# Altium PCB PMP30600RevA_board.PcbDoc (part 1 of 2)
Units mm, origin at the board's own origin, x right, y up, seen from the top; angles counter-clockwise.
Board outline 78.5 x 61.5 mm, 4 copper layers (Top Layer, 2nd Layer, 3rd Layer, Bottom Layer), stack 2.155 mm thick; 62 components, 27 nets, 174 pads, 413 vias.
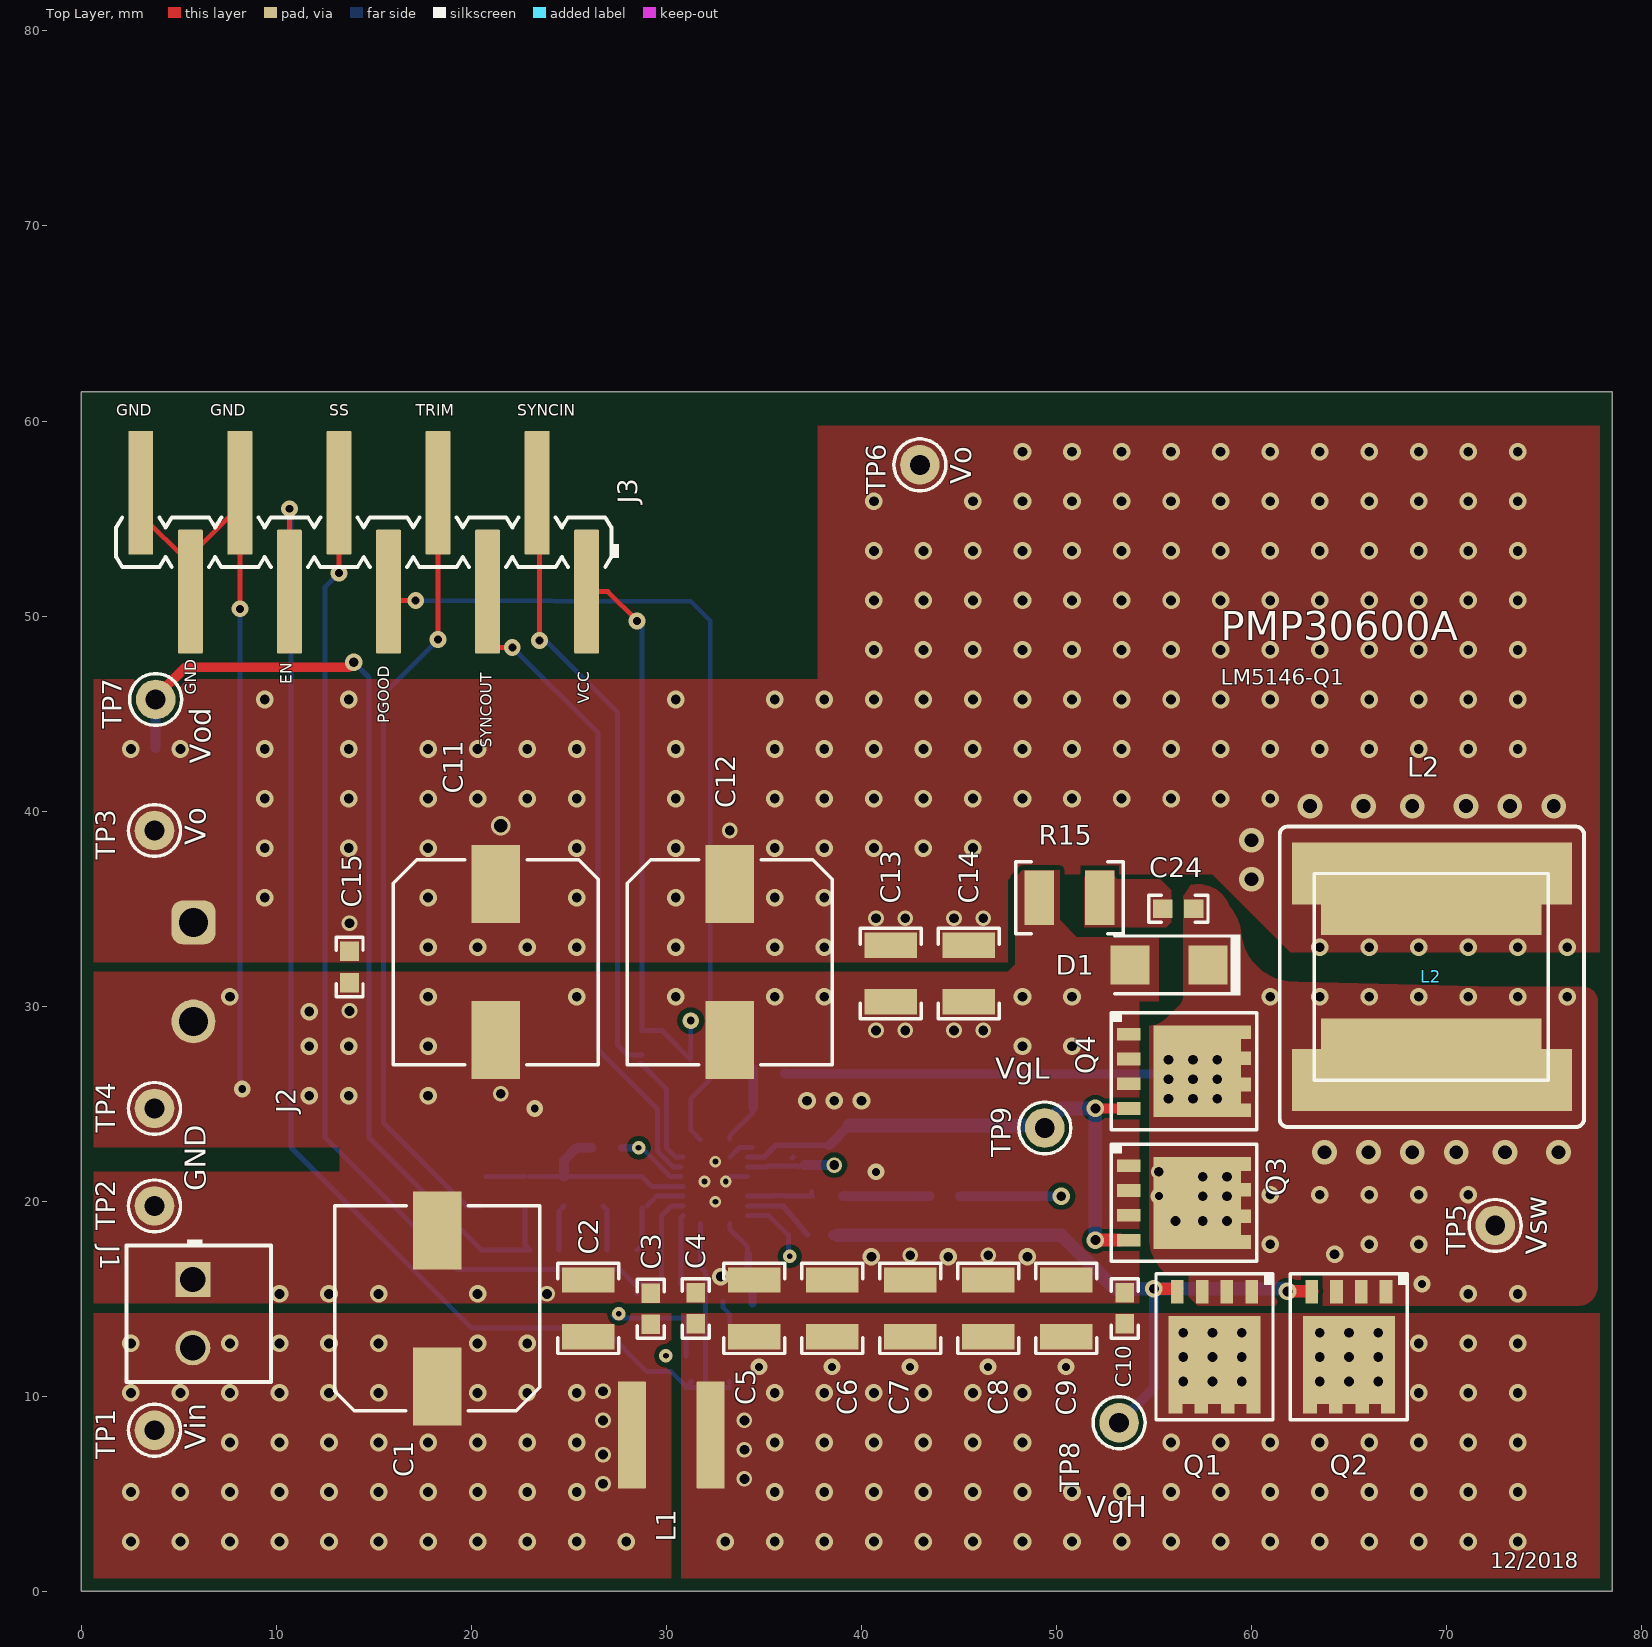
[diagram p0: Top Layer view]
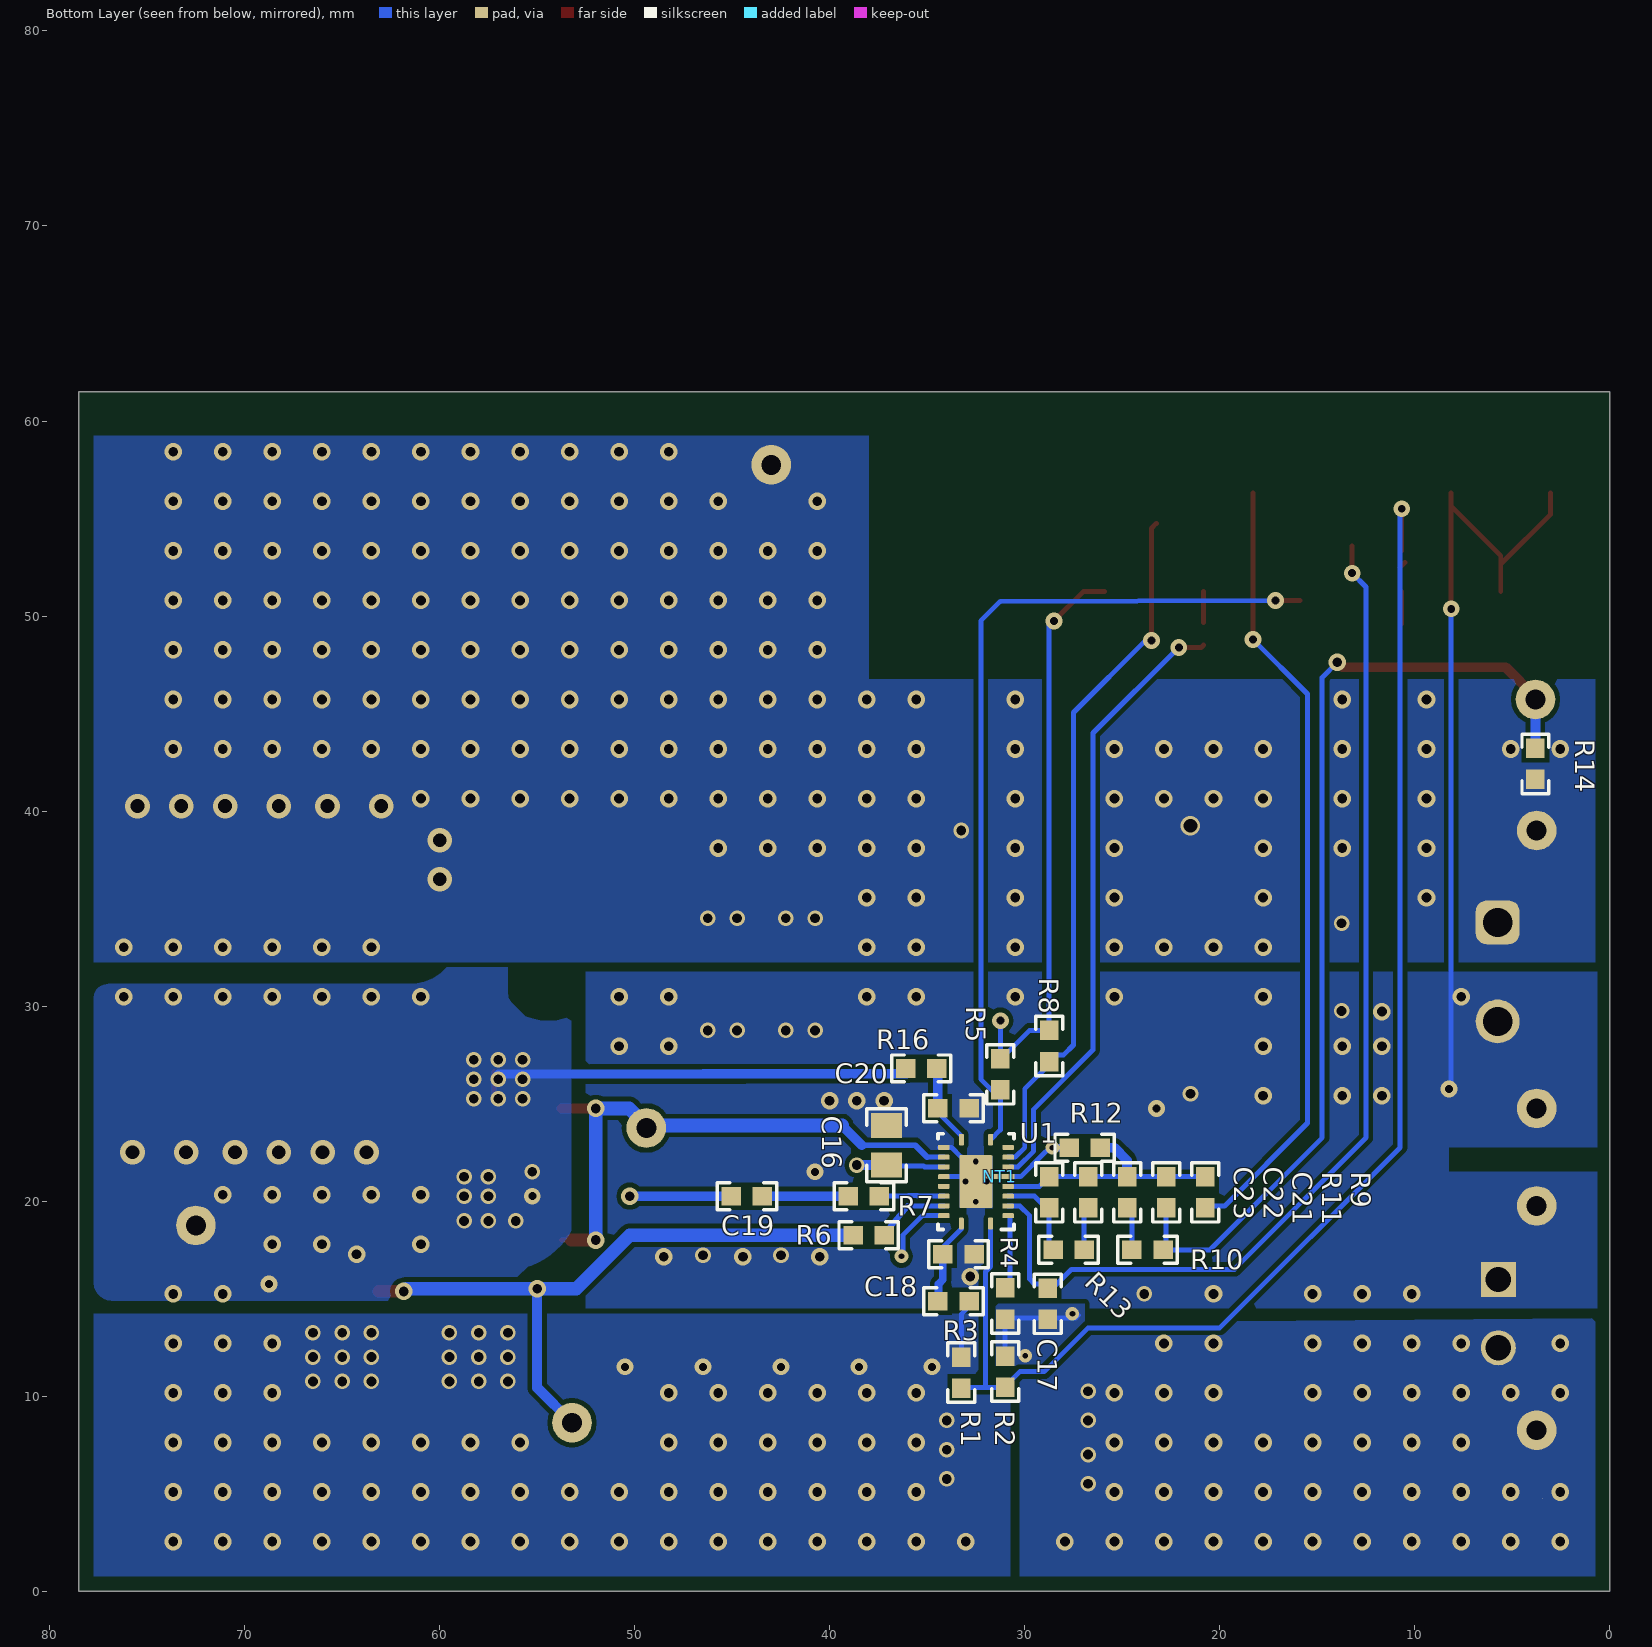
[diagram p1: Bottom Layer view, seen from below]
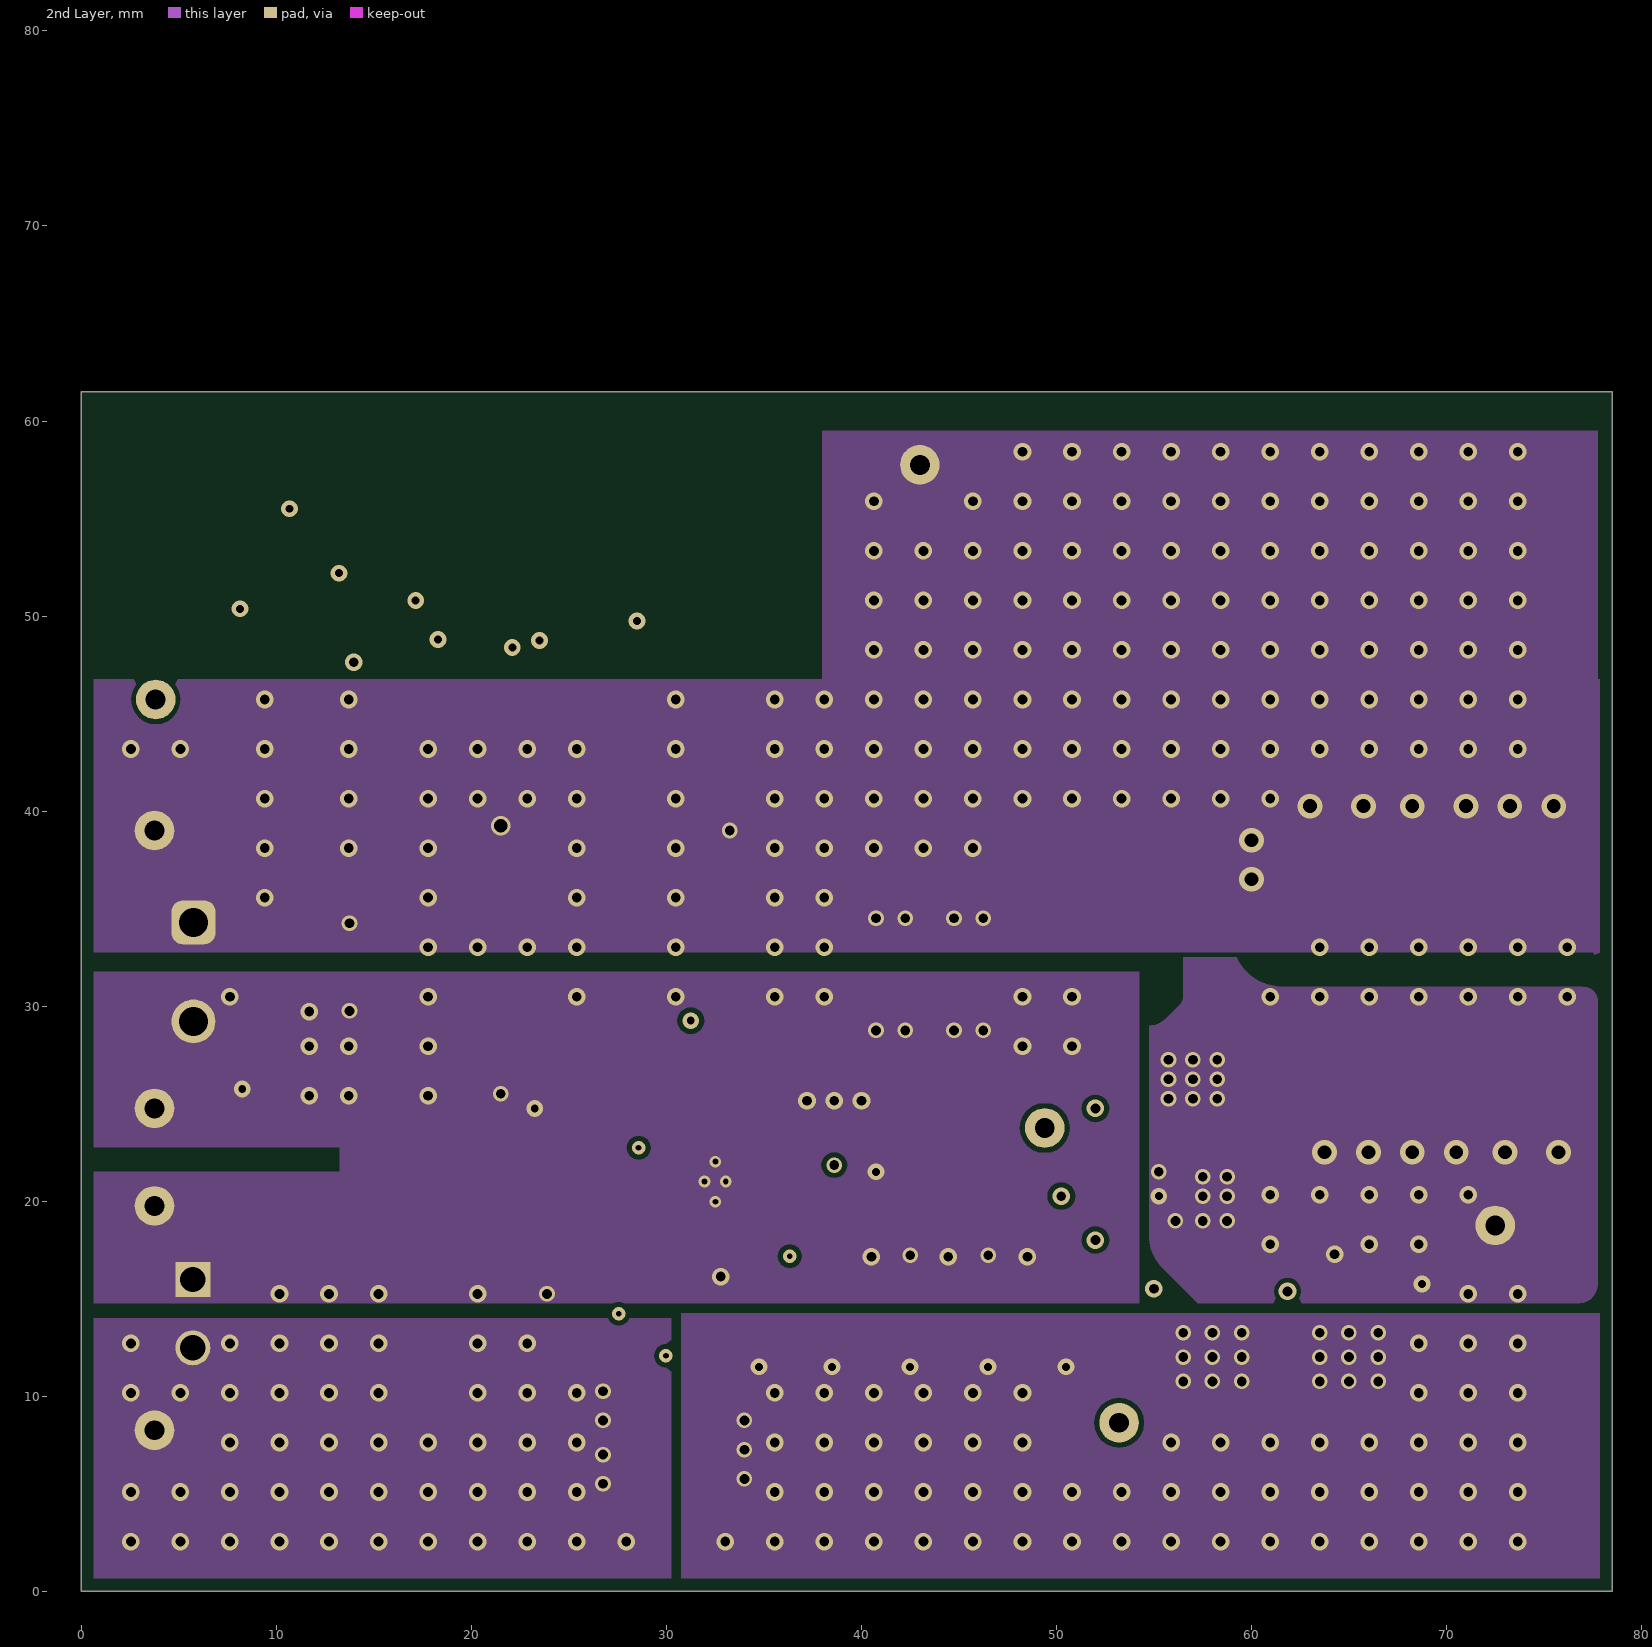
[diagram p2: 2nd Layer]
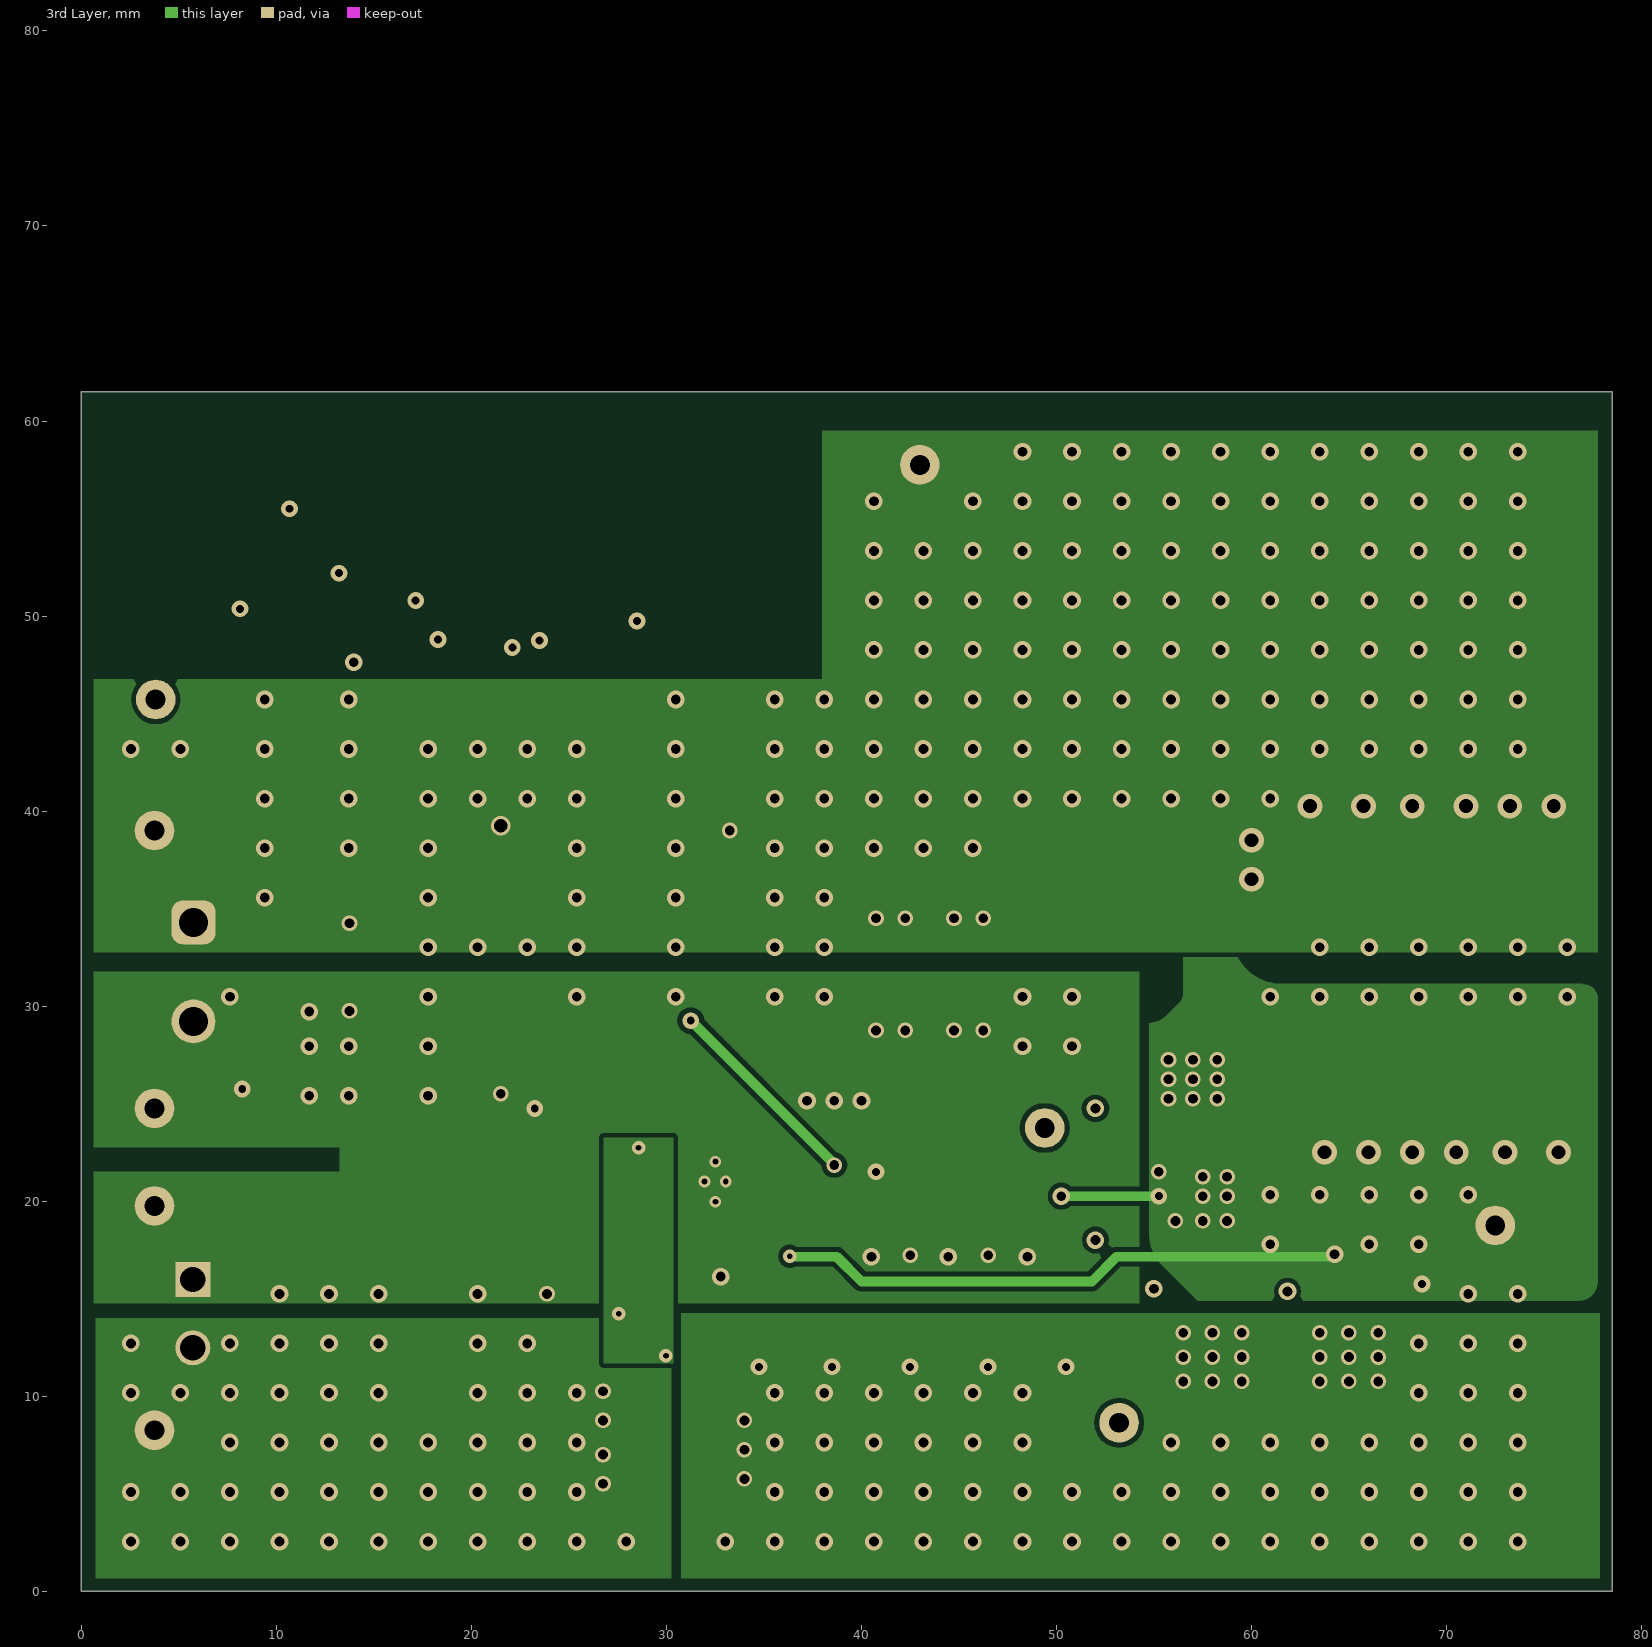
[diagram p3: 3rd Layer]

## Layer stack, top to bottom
Top Solder: solder mask 0.0102, Solder Resist, Dk 3.5
Top Layer: signal copper 0.0356
Dielectric 2: dielectric 0.254, Dk 4.2
2nd Layer: signal copper 0.036
Dielectric1: core 1.5037, FR-4, Dk 4.8
3rd Layer: signal copper 0.036
Dielectric 3: dielectric 0.254, Dk 4.2
Bottom Layer: signal copper 0.0356
Bottom Solder: solder mask 0.0102, Solder Resist, Dk 3.5

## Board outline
0,0 78.5,0 78.5,61.5 0,61.5
cut-out: 3.442,4.75
cut-out: 3.442,4.75

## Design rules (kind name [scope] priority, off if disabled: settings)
AcuteAngle [All] p1: minimum=4.50000000000000E+0001 checktracksonly=FALSE
AssemblyTestPointUsage [All] p1: valid=2
BoardOutlineClearance BoardOutlineClearance_MountingHoles [OnCopper and InComponentClass('Mounting Holes')] p1: gap=1 ignorepadtopadclearanceinfootprint=FALSE
BoardOutlineClearance BoardOutlineClearance_Poly [OnCopper and IsPoly] p2: gap=0.635 ignorepadtopadclearanceinfootprint=FALSE
BoardOutlineClearance [OnCopper and Not InComponentClass('Logo') and not InComponentClass('FiducialMark') and not InRegion(1000,500,4000,800) and not InPoly] p3: gap=1.905 ignorepadtopadclearanceinfootprint=FALSE
Clearance Clearance_Keepouts [((IsTrack Or IsArc) And Not InPoly) And IsFree and IsKeepOut vs ((IsTrack Or IsArc) And Not InPoly) And IsFree and IsKeepOut] p1: gap=0 ignorepadtopadclearanceinfootprint=FALSE
Clearance Clearance_Poly [InPolygon] p2: gap=0.25 ignorepadtopadclearanceinfootprint=TRUE
Clearance Clearance_FiducialMark [IsKeepOut and InComponentClass('FiducialMark') vs IsPad and InComponentClass('FiducialMark')] p3: gap=0 ignorepadtopadclearanceinfootprint=FALSE
Clearance [All] p4: gap=0.2 ignorepadtopadclearanceinfootprint=TRUE
ComponentClearance ComponentClearance_MountingHoles_FiducialMarks [InComponentClass('Mounting Holes') vs InComponentClass('FiducialMark')] p1: gap=1.27 collisioncheckmode=3 verticalgap=0.254 showdistances=FALSE
ComponentClearance ComponentClearance_Shunt [InComponentClass('Header') vs InComponentClass('Shunt')] p2: gap=0 collisioncheckmode=3 verticalgap=0 showdistances=FALSE
ComponentClearance ComponentClearance_Logo [InComponentClass('Logo')] p3: gap=1.27 collisioncheckmode=3 verticalgap=0.254 showdistances=FALSE
ComponentClearance ComponentClearance_ScrewToNut [(HasFootprint('NY PMS 440 0025 PH')) vs (HasFootprint('Keystone_1902C'))] p4: gap=0.127 collisioncheckmode=3 verticalgap=0.254 showdistances=FALSE
ComponentClearance ComponentClearance_MountingHoles [InComponentClass('Mounting Holes')] p5: gap=6.35 collisioncheckmode=3 verticalgap=2540 showdistances=FALSE
ComponentClearance ComponentClearance_SmallPassives [HasFootprint('0201*') or HasFootprint('0402*') or HasFootprint('0508') or HasFootprint('0603*') or HasFootprint('0612') or HasFootprint('0805*') or HasFootprint('0815*') or HasFootprint('0830*') or HasFootprint('1206*') or HasFootprint('1210*') or HasFootprint('1808*') or HasFootprint('1812*') or HasFootprint('1825*') or HasFootprint('2010*') or HasFootprint('2220*') or HasFootprint('2225*') or HasFootprint('2512*') or HasFootprint('2728*') or HasFootprint('3518*') vs HasFootprint('0201*') or HasFootprint('0402*') or HasFootprint('0508') or HasFootprint('0603*') or HasFootprint('0612') or HasFootprint('0805*') or HasFootprint('0815*') or HasFootprint('0830*') or HasFootprint('1206*') or HasFootprint('1210*') or HasFootprint('1808*') or HasFootprint('1812*') or HasFootprint('1825*') or HasFootprint('2010*') or HasFootprint('2220*') or HasFootprint('2225*') or HasFootprint('2512*') or HasFootprint('2728*') or HasFootprint('3518*')] p6: gap=0.38 collisioncheckmode=3 verticalgap=0.254 showdistances=FALSE
ComponentClearance ComponentClearance_THtoSMT [IsThruComponent vs IsSMTComponent] p7: gap=1.016 collisioncheckmode=3 verticalgap=0.762 showdistances=FALSE
ComponentClearance ComponentClearance_THtoTH [IsThruComponent vs IsThruComponent] p8: gap=0.762 collisioncheckmode=3 verticalgap=0.762 showdistances=FALSE
ComponentClearance [All] p9: gap=0.762 collisioncheckmode=3 verticalgap=0.254 showdistances=FALSE
DiffPairsRouting [All] p1: maxlimit=2.54 minlimit=0.254 mostfreqgap=0.254 toplayer_minwidth=0.381 toplayer_maxwidth=0.381 toplayer_prefwidth=0.381 midlayer1_minwidth=0.381 midlayer1_maxwidth=0.381 midlayer1_prefwidth=0.381 midlayer2_minwidth=0.381 midlayer2_maxwidth=0.381 midlayer2_prefwidth=0.381 bottomlayer_minwidth=0.381 bottomlayer_maxwidth=0.381 bottomlayer_prefwidth=0.381 maxuncoupledlength=25.4
FabricationTestPointUsage TestPointUsage [All] p1: valid=2 allowmultiple=FALSE
FabricationTestpoint Testpoint [All] p1: side=3 testpointundercomponent=TRUE minsize=1.016 maxsize=2.54 preferedsize=1.524 minholesize=0 maxholesize=1.016 preferedholesize=0.813 testpointgrid=0.025 allowsidetop=TRUE allowsidebottom=TRUE usegrid=TRUE gridtolerance=0
FanoutControl Fanout_LCC [IsLCC] p1: bgadir=Out bgaviamode=Centered fanoutstyle=Auto fanoutdirection=Alternating viagrid=0.025 // Fanout_LCC (Default Rule)
FanoutControl Fanout_BGA [IsBGA] p2: bgadir=Out bgaviamode=Centered fanoutstyle=Auto fanoutdirection=Alternating viagrid=0.025 // Fanout_BGA (Default Rule)
FanoutControl Fanout_Default [All] p4: bgadir=Out bgaviamode=Centered fanoutstyle=Auto fanoutdirection=Alternating viagrid=0.025 // Fanout_Default (Default Rule)
FanoutControl Fanout_Small [(CompPinCount < 5)] p5: bgadir=Out bgaviamode=Centered fanoutstyle=Auto fanoutdirection=OutThenIn viagrid=0.025 // Fanout_Small (Default Rule)
HoleSize [All] p1: absolutevalues=TRUE maxlimit=6.375 minlimit=0.3 maxpercent=80.000 minpercent=20.000
MinimumAnnularRing MinimumAnnularRing_ThermalPadVias [IsVia and InAnyComponent] p1: minimumring=0.15
MinimumAnnularRing [All] p2: minimumring=0.15
MinimumSolderMaskSliver MinimumSolderMaskSliver_Logo [InComponentClass('Logo') vs InComponentClass('Logo')] p1: minsoldermaskwidth=0.018
MinimumSolderMaskSliver [All] p2: minsoldermaskwidth=0.1
PlaneConnect [All] p1: planeconnectstyle=Relief reliefexpansion=0.254 reliefentries=4 reliefconductorwidth=0.254 reliefairgap=0.254
PolygonConnect [All] p1: connectstyle=Direct reliefconductorwidth=0.254 reliefentries=4 polygonreliefangle="90 Angle" airgapwidth=0.254
RoutingVias ThermalPadVias [IsVia and InAnyComponent] p1: holewidth=0.3 width=0.5 viastyle="Through Hole" minholewidth=0.3 minwidth=0.6 maxholewidth=0.5 maxwidth=1
RoutingVias [All] p2: holewidth=0.406 width=0.864 viastyle="Through Hole" minholewidth=0.3 minwidth=0.66 maxholewidth=1.016 maxwidth=1.651
SilkToBoardRegionClearance [Not ((IsComment or IsDesignator) And (Hide <> 'False')) and not InRegion(1000,500,4000,800)] p1:
SilkToSilkClearance SilkToSilkClearance_Pb-FreeLogo [(HasFootprint('Pb-Free_Overlay_Medium') OR HasFootprint('Pb-Free_Overlay_Small')) vs (HasFootprint('Pb-Free_Overlay_Medium') OR HasFootprint('Pb-Free_Overlay_Small'))] p1: silktosilkclearance=0
SilkToSilkClearance [All] p2: silktosilkclearance=0.1
SilkToSolderMaskClearance SilkToComponentPadClearance [(IsPad or IsFill or IsRegion) and InAnycomponent] p1: minsilkscreentomaskgap=0.127 clearancetoexposedcopper=TRUE
SilkToSolderMaskClearance "Silk to Solder Mask Opening" [All] p2: minsilkscreentomaskgap=0.1 clearancetoexposedcopper=FALSE
SolderMaskExpansion [All] p1: expansion=0.05
UnRoutedNet [All] p1: checkbadconnections=TRUE
Width [All] p1: maxlimit=2.54 minlimit=0.152 preferedwidth=0.254 checkconnectedcopper=TRUE
14 further rules are at their usual default settings.

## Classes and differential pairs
component class Header: J3

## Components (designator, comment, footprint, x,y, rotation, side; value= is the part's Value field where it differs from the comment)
C1 "EEHZC1K470P" SM_RADIAL_10BMM 18.25,14.5 r90 top value=330uF
C2 "Capacitor" 1210_270 26,14.5 r90 top value=10uF
C3 "Capacitor" 0603 29.21,14.478 r90 top value=0.1uF
C4 "Capacitor" 0603 31.5,14.5 r90 top value=0.1uF
C5 "Capacitor" 1210_270 34.5,14.5 r90 top value=10uF
C6 "Capacitor" 1210_270 38.5,14.5 r90 top value=10uF
C7 "Capacitor" 1210_270 42.5,14.5 r90 top value=10uF
C8 "Capacitor" 1210_270 46.5,14.5 r90 top value=10uF
C9 "Capacitor" 1210_270 50.5,14.5 r90 top value=10uF
C10 "Capacitor" 0603 53.5,14.5 r90 top value=0.1uF
C11 "EEHZC1E331P" SM_RADIAL_10BMM 21.25,32.25 r270 top value=330uF
C12 "EEHZC1E331P" SM_RADIAL_10BMM 33.25,32.25 r270 top value=330uF
C13 "Capacitor" 1210_270 41.5,31.661 r270 top value=47uF
C14 "Capacitor" 1210_270 45.5,31.661 r270 top value=47uF
C15 "Capacitor" 0603 13.75,32 r270 top value=0.1uF
C16 "C0805C225K8RACTU" 0805_HV 37.084,22.86 r90 bottom value=2.2uF
C17 "Capacitor" 0603 28.829,14.732 r270 bottom value=0.1uF
C18 "Capacitor" 0603 33.401,17.272 r0 bottom value=0.1uF
C19 "Capacitor" 0603 44.25,20.25 r180 bottom value=0.1uF
C20 "Capacitor" 0603 33.655,24.765 r0 bottom value=0.1uF
C21 "Capacitor" 0603 24.75,20.45 r270 bottom value=0.1uF
C22 "Capacitor" 0603 26.75,20.45 r270 bottom value=0.1uF
C23 "Capacitor" 0603 28.75,20.45 r270 bottom value=0.1uF
C24 "Capacitor" 0603 56.25,35 r180 top value=1500pF
D1 "DIODE_SCHOTTKY" SMA 55.779,32.106 r180 top value=40V
J1 "691214110002" Wurth_691214110002 5.715,14.224 r270 top
J2 "691236510002" Wurth_691236510002 5.75,31.75 r270 top
J3 "GBC10SABN-M30" Sullins_GBC10SABN-M30 14.48,53.785 r180 top
L1 "XAL6060-472MEB" XAL6060 30.25,8 r180 top value=4.7uH
L2 "XAL1010-472MEB" XAL1010 69.215,31.495 r90 top value=4.7uH
L2 "XAL1580-302MEB" XAL1580 69.25,31.5 r90 top value=3uH
NT1 "Net-Tie" Net-Tie_10milWide_30milLong 31.293,21.25 r0 bottom net-tie
Q1 "MOSFET_N_D56789G4S123" PG-TDSON-8 58.106,12.531 r270 top value=40V
Q2 "MOSFET_N_D56789G4S123" PG-TDSON-8 65,12.531 r270 top value=40V
Q3 "MOSFET_N_D56789G4S123" PG-TDSON-8 56.543,19.902 r0 top value=40V
Q4 "MOSFET_N_D56789G4S123" PG-TDSON-8 56.543,26.652 r0 top value=40V
R1 "CR0603-FX-4991ELF" 0603 33.25,11.2 r90 bottom value=4.99k
R2 "CR0603-FX-4991ELF" 0603 31,11.25 r270 bottom value=4.99k
R3 "CR0603-FX-4991ELF" 0603 33.655,14.859 r180 bottom value=4.99k
R4 "CR0603-FX-4991ELF" 0603 31,14.75 r90 bottom value=4.99k
R5 "CR0603-FX-4991ELF" 0603 31.25,26.5 r90 bottom value=4.99k
R6 "CR0603-FX-4991ELF" 0603 38,18.25 r180 bottom value=4.99k
R7 "CR0603-FX-4991ELF" 0603 38.25,20.25 r180 bottom value=4.99k
R8 "CR0603-FX-4991ELF" 0603 28.75,27.95 r270 bottom value=4.99k
R9 "CR0603-FX-4991ELF" 0603 20.75,20.45 r90 bottom value=4.99k
R10 "CR0603-FX-4991ELF" 0603 23.7,17.5 r180 bottom value=4.99k
R11 "CR0603-FX-4991ELF" 0603 22.75,20.45 r270 bottom value=4.99k
R12 "CR0603-FX-4991ELF" 0603 26.924,22.733 r180 bottom value=4.99k
R13 "CR0603-FX-4991ELF" 0603 27.75,17.5 r180 bottom value=4.99k
R14 "CR0603-FX-4991ELF" 0603 3.81,42.418 r270 bottom value=4.99k
R15 "Resistor" 1210M 50.673,35.56 r0 top value=2.00
R16 "CR0603-FX-4991ELF" 0603 35.306,26.797 r180 bottom value=4.99k
TP1 "5000" Keystone5000 3.75,8.25 r90 top
TP2 "5001" Keystone5001 3.75,19.75 r90 top
TP3 "5000" Keystone5000 3.75,39 r90 top
TP4 "5001" Keystone5001 3.75,24.75 r90 top
TP5 "5003" Keystone5003 72.5,18.75 r90 top
TP6 "5002" Keystone5002 43,57.75 r90 top
TP7 "5002" Keystone5002 3.81,45.72 r90 top
TP8 "5002" Keystone5002 53.213,8.636 r90 top
TP9 "5002" Keystone5002 49.403,23.749 r90 top
U1 "LM5146QRGYRQ1" RGY0020B 32.5,21 r0 bottom

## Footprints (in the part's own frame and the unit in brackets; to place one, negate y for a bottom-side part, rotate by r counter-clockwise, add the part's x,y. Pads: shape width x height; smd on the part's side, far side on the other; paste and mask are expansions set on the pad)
0603 [mm] "0603 from SM-752 data"
  rect 1x0.95 smd: 1(-0.8,0) 2(0.8,0)
  silkscreen extent -1.52,-0.69 1.52,0.69, body extent -0.87,-0.47 0.87,0.47, height 1
0805_HV [mil] "0805 with 30mil clearance between pads"
  rect 50x63 smd: 1(-40,0) 2(40,0)
  silkscreen extent -74,-40 74,40, body extent -43,-29 43,29, height 57
1210_270 [mm] "1210"
  rect 1.3x2.7 smd: 1(-1.45,0) 2(1.45,0)
  silkscreen extent -2.32,-1.57 2.32,1.57, body extent -1.7,-1.35 1.7,1.35, height 2.7
1210M [mm] "1210 from SM-752 data"
  rect 1.5x2.8 smd: 1(-1.55,0) 2(1.55,0)
  silkscreen extent -2.75,-1.85 2.75,1.85, body extent -1.7,-1.35 1.7,1.35, height 1.35
Keystone5000 [mil] "For Keystone 500x miniature loop terminals"
  round 80 hole 40: 1(0,0)
  silkscreen extent -52,-52 52,52, body extent -49,-49 49,49, height 182
Keystone5001 [mil] "For Keystone 500x miniature loop terminals"
  round 80 hole 40: 1(0,0)
  silkscreen extent -52,-52 52,52, body extent -49,-49 49,49, height 182
Keystone5002 [mil] "For Keystone 500x miniature loop terminals"
  round 80 hole 40: 1(0,0)
  silkscreen extent -52,-52 52,52, body extent -49,-49 49,49, height 182
Keystone5003 [mil] "For Keystone 500x miniature loop terminals"
  round 80 hole 40: 1(0,0)
  silkscreen extent -52,-52 52,52, body extent -49,-49 49,49, height 182
Net-Tie_10milWide_30milLong [mil] "10mil net tie, no solder mask opening, no solder paste"
  rect 30x10 smd paste-5 mask-5: 1(-15,0) 2(15,0)
PG-TDSON-8 [mm] "Infineon recommended land pattern"
  rect 1.2x0.65 smd: 1(-2.825,1.905) 2(-2.825,0.635) 3(-2.825,-0.635) 4(-2.825,-1.905)
  rect 0.5x0.7 smd: 5(3.175,-2) 6(3.175,-0.675) 7(3.175,0.675) 8(3.175,2)
  rect 4.5x4.7 smd paste-2.25: 9(0.675,0)
  silkscreen extent -3.74,-3 3.74,3, body extent -3.18,-2.89 3.18,2.9, height 1.1
RGY0020B [mm] "QFN, 20-Leads, Body 4.5x3.5mm, Pitch 0.5mm, Thermal Pad 2.7x1.7mm"
  rrect40% 0.25x0.6 smd: 1(-0.75,2.15) 10(-0.75,-2.15) 11(0.75,-2.15) 20(0.75,2.15)
  rrect40% 0.6x0.25 smd: 2(-1.65,1.75) 3(-1.65,1.25) 4(-1.65,0.75) 5(-1.65,0.25) 6(-1.65,-0.25) 7(-1.65,-0.75) 8(-1.65,-1.25) 9(-1.65,-1.75) 12(1.65,-1.75) 13(1.65,-1.25) 14(1.65,-0.75) 15(1.65,-0.25) 16(1.65,0.25) 17(1.65,0.75) 18(1.65,1.25) 19(1.65,1.75)
  rrect13% 0.75x1.21 on Bottom Paste: 21(-0.475,-0.705) 21(-0.475,0.705) 21(0.475,-0.705) 21(0.475,0.705)
  rrect6% 1.7x2.7 smd paste-1.4: 21(0,0)
  silkscreen extent -1.95,-2.45 1.95,2.45, body extent -1.75,-2.25 1.75,2.25, height 0.9
SM_RADIAL_10BMM [mm] "Nichicon 10x10"
  rect 4x2.5 smd: 1(-4,0) 2(4,0)
  silkscreen extent -5.25,-5.25 5.25,5.25, body extent -5.25,-5.25 5.25,5.25, height 10.5
SMA [mm] "Molded Diode, 2-Leads, Body 4.3x2.6mm, IPC Medium Density, based on OnSemi component dimensions and land pattern"
  rect 2x2 smd: 1(-2,0) 2(2,0)
  silkscreen extent -3.66,-1.57 2.79,1.57, body extent -2.6,-1.3 2.6,1.3, height 2.42
Sullins_GBC10SABN-M30 [mm] "Header, 2.54mm, 10x1, SMT"
  rrect8% 1.27x6.35 smd: 1(-11.43,2.535) 2(-8.89,-2.535) 3(-6.35,2.535) 4(-3.81,-2.535) 5(-1.27,2.535) 6(1.27,-2.535) 7(3.81,2.535) 8(6.35,-2.535) 9(8.89,2.535) 10(11.43,-2.535)
  silkscreen extent -13.1,-1.27 12.7,1.27, body extent -12.7,-4.06 12.7,4.06, height 10.19
Wurth_691214110002 [mm] "Receptacle, 3.5mm, 2x1, TH"
  rect 1.8x1.8 hole 1.3: 1(-1.75,0)
  round 1.8 hole 1.3: 2(1.75,0)
  silkscreen extent -3.8,-3.4 3.5,4, body extent -3.9,-3.4 3.5,4, height 8.5
Wurth_691236510002 [mm] "Terminal Block, 5.08mm, 2x1, R/A, TH"
  rrect50% 2.25x2.25 hole 1.5: 1(-2.54,0)
  round 2.25 hole 1.5: 2(2.54,0)
  body extent -5.68,-5.5 5.08,5.85, height 18
XAL1010 [mm] "COILCRAFT"
  rect 2.38x11.31 smd: 1(-3.325,0) 2(3.325,0)
  silkscreen extent -5.3,-6 5.3,6, body extent -5.25,-5.9 5.25,5.9, height 10
XAL1580 [mm] "COILCRAFT"
  rect 3.18x14.36 smd: 1(-5.3,0) 2(5.3,0)
  silkscreen extent -7.7,-7.8 7.7,7.8, body extent -7.7,-7.8 7.7,7.8, height 8
XAL6060 [mm] "Coilcraft recommended land pattern Document 887-4 Revised 01/14/18"
  rrect7% 1.43x5.5 smd: 1(-2.019,0) 2(2.019,0)
  body extent -3.28,-3.38 3.28,3.38, height 6.11

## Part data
C1: library part CMP-0012593-1, "CAP, Polymer Hybrid, 47 uF, 80 V, +/- 20%, 36 ohm, 10x10 SMD", Manufacturer=Panasonic, PartNumber=EEHZC1E331P, Supplier Part Number 1=P15459CT-ND, Tolerance_%=20%, Value1="20 ohm", Value2=25V, ValueDisplayed=330uF
C2 C5 C6 C7 C8 C9: library part CMP-0009226-3, "CAP, CERM, 10 uF, 50 V, +/- 10%, X7R, 1210", Cap_Case=1210, Manufacturer=MuRata, PartNumber=GRM32ER71H106KA12L, Supplier Part Number 1=490-6544-1-ND, TempCo=X7R, Tolerance_%=10%, Value1=Unknown, Value2=50V, ValueDisplayed=10uF
C3 C4 C10: library part CMP-0007434-4, "CAP, CERM, 0.1 uF, 50 V, +/- 10%, X7R, 0603", Cap_Case=0603, Manufacturer=MuRata, PartNumber=GRM188R71H104KA93D, Supplier Part Number 1=490-1519-1-ND, TempCo=X7R, Tolerance_%=10%, Value1=Unknown, Value2=50V, ValueDisplayed=0.1uF
C11 C12: library part CMP-0012593-1, "CAP, Polymer Hybrid, 330 uF, 25 V, +/- 20%, 20 ohm, 10x10 SMD", Manufacturer=Panasonic, Supplier Part Number 1=P15459CT-ND, Tolerance_%=20%, Value1="20 ohm", Value2=25V, ValueDisplayed=330uF
C13 C14: library part CMP-0009220-2, "CAP, CERM, 47 uF, 10 V, +/- 10%, X7R, 1210", Cap_Case=1210, Manufacturer=MuRata, PartNumber=GRM32ER71A476KE15L, Supplier Part Number 1=490-5312-1-ND, TempCo=X7R, Tolerance_%=10%, Value1=Unknown, Value2=10V, ValueDisplayed=47uF
C15 C17 C18 C19 C20 C21 C22 C23: library part CMP-0007469-4, "CAP, CERM, 0.1 uF, 100 V, +/- 10%, X7R, 0603", Cap_Case=0603, Manufacturer=MuRata, PartNumber=GRM188R72A104KA35D, Supplier Part Number 1=490-3285-1-ND, TempCo=X7R, Tolerance_%=10%, Value1=Unknown, Value2=100V, ValueDisplayed=0.1uF
C16: library part CMP-0007772-1, "CAP, CERM, 2.2 uF, 10 V, +/- 10%, X7R, 0805", Cap_Case=0805, Manufacturer=Kemet, Supplier Part Number 1=399-3522-1-ND, TempCo=X7R, Tolerance_%=10%, Value1="0.008 ohm", Value2=10V, ValueDisplayed=2.2uF
C24: library part CMP-0007472-4, "CAP, CERM, 1500 pF, 100 V, +/- 10%, X7R, 0603", Cap_Case=0603, Manufacturer=MuRata, PartNumber=GRM188R72A152KA01D, Supplier Part Number 1=490-1475-1-ND, TempCo=X7R, Tolerance_%=10%, Value1=Unknown, Value2=100V, ValueDisplayed=1500pF
D1: library part CMP-0028353-2, "Diode, Schottky, 40 V, 3 A, SMA", Manufacturer="Diodes Inc.", PartNumber=B340A-13-F, Value1=3A, Value2=0.5V
J1: library part CMP-0054825-2, "Terminal Block, 3.5mm, 2x1, Tin, TH", Color=Green, Current_A=10A, Manufacturer="Wurth Elektronik", Supplier Part Number 1=732-2747-ND, Voltage_V=300V
J2: library part CMP-0079044-1, "Terminal Block, 5.08mm, 2x1, R/A, TH", Color=Green, Current_A=20A, Manufacturer="Wurth Elektronik", Supplier Part Number 1=732-10995-ND, Voltage_V=300V
J3: library part CMP-0054626-1, "Header, 2.54mm, 10x1, Gold, SMT", Color=Black, Current_A=3A, Manufacturer="Sullins Connector Solutions", Supplier Part Number 1=S1033E-10-ND, Voltage_V=600V
L1: library part CMP-0061020-2, "Inductor, Shielded, Composite, 4.7 µH, 10.5 A, 0.0144 ohm, AEC-Q200 Grade 1, SMD", Manufacturer=Coilcraft, Value1="0.0144 ohm", Value2=10.5A, ValueDisplayed=4.7uH
L2: library part CMP-0060950-1, "Inductor, Shielded, Composite, 4.7 uH, 24 A, 0.01 ohm, SMD", Manufacturer=Coilcraft, Supplier Part Number 1=994-XAL1010-472MEB, Value1="0.01 ohm", Value2=24A, ValueDisplayed=4.7uH
L2: library part CMP-0060977-1, "Inductor, Shielded, Composite, 3 uH, 34.4 A, 0.002619 ohm, SMD", Manufacturer=Coilcraft, Value1="0.002619 ohm", Value2=34.4A, ValueDisplayed=3uH
NT1: library part CMP-0078142-1, "Single point connection between nets.", Manufacturer=N/A
Q1 Q2 Q3 Q4: library part CMP-0000689-1, "MOSFET, N-CH, 40 V, 73 A, PG-TDSON-8", Alternate Manufacturer=None, Manufacturer="Infineon Technologies", PartNumber="BSC059N04LS G", Supplier Part Number 1="BSC059N04LS G-ND", Value1=0.008, Value2="30 nC"
R1 R2 R3 R4 R5 R6 R7 R8 R9 R10 R11 R12 R13 R14 R16: library part CMP-0021989-1, "RES, 4.99 k, 1%, 0.1 W, 0603", Manufacturer=Bourns, Power_W=100mW, Supplier Part Number 1=CR0603-FX-4991ELFTR-ND, TempCo="100 ppm/C", Tolerance_%=1%, Value2=0.1W, Value_Code=4k99, ValueDisplayed=4.99k
R15: library part CMP-0015029-2, "RES, 2.00, 1%, 0.5 W, AEC-Q200 Grade 0, 1210", Manufacturer=Panasonic, PartNumber=ERJ-14BQF2R0U, Power_W=500mW, Supplier Part Number 1=P17258CT-ND, TempCo="100 ppm/C", Tolerance_%=1%, Value2=0.5W, Value_Code=2R00, ValueDisplayed=2.00
TP1 TP3: library part CMP-0055137-1, "Test Point, Miniature, Red, TH", Color=Red, Manufacturer=Keystone, Supplier Part Number 1=36-5000-ND
TP2 TP4: library part CMP-0055138-1, "Test Point, Miniature, Black, TH", Color=Black, Manufacturer=Keystone, Supplier Part Number 1=36-5001-ND
TP5: library part CMP-0055140-1, "Test Point, Miniature, Orange, TH", Color=Orange, Manufacturer=Keystone, Supplier Part Number 1=36-5003-ND
TP6 TP7 TP8 TP9: library part CMP-0055139-1, "Test Point, Miniature, White, TH", Color=White, Manufacturer=Keystone, Supplier Part Number 1=36-5002-ND
U1: library part CMP-0081848-1, "5.5-V to 100-V Synchronous Buck Controller With Wide Duty Cycle Range, RGY0020B (VQFN-20)", Alternate Manufacturer="Texas Instruments", Alternate PartNumber=LM5146QRGYTQ1

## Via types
v1: diameter 0.9, hole 0.5, Top Layer to Bottom Layer, 251 vias
v2: diameter 0.9, hole 0.5, Top Layer to Bottom Layer, tented top, 61 vias
v3: diameter 0.8, hole 0.5, Top Layer to Bottom Layer, 57 vias
v4: diameter 0.864, hole 0.406, Top Layer to Bottom Layer, 18 vias
v5: diameter 1.27, hole 0.711, Top Layer to Bottom Layer, 14 vias
v6: diameter 0.6, hole 0.3, Top Layer to Bottom Layer, 4 vias
v7: diameter 0.7, hole 0.3, Top Layer to Bottom Layer, 2 vias
v8: diameter 0.9, hole 0.5, Top Layer to Bottom Layer, tented both sides, 1 vias
v9: diameter 0.7, hole 0.3, Top Layer to Bottom Layer, tented both sides, 1 vias
v10: diameter 0.7, hole 0.3, Top Layer to Bottom Layer, tented bottom, 1 vias
v11: diameter 0.864, hole 0.406, Top Layer to Bottom Layer, tented top, 1 vias
v12: diameter 1, hole 0.7, Top Layer to Bottom Layer, 1 vias
v13: diameter 0.8, hole 0.5, Top Layer to Bottom Layer, tented top, 1 vias

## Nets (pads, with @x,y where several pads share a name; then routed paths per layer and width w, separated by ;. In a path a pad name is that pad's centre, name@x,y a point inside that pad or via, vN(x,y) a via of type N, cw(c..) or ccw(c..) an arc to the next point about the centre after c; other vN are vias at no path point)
AGND: C17.2 NT1.1 R2.1 R4.1 R12.1 U1.6 | length 9.4
  Bottom Layer w0.254: v9@27.25,14.144 27.394,14 31,14 R2.1@31,12.05 ; v10(28.575,22.733) 28.725,22.733 29.092,22.366 30.208,21.25 NT1.1@30.75,21.25
  Bottom Layer w0.4: R12.1@27.724,22.733 v10(28.575,22.733)
  other v7: 29.972,12.065
  other v9: 27.559,14.224
EN: J3.7 R1.1 R2.2 U1.1 | length 74.1
  Top Layer w0.254: J3.7@10.5,52.75 J3.7@10.75,52.5 ; J3.7@10.668,53.34 v4(10.668,55.499) ; J3.7@10.67,49.58 J3.7@10.67,51.25
  Bottom Layer w0.254: v4@10.668,55.626 10.75,55.544 10.75,22.759 ; 10.75,22.75 20,13.5 26.75,13.5 29,11.25 30.25,11.25 R2.2@31,10.5 ; R2.2@31.25,10.5 R2.2@31.05,10.5 ; R2.2@31.25,10.75 31.3,10.75 R2.2@31.05,10.5 ; U1.1@31.75,18.85 31.75,16.637 32.004,16.383 32.004,10.668 ; 32,10.5 32,10.75 ; R1.1@33.2,10.75 33.225,10.725 R1.1@33.25,10.75 ; R1.1@33.25,10.5 33.2,10.45 R2.2@31,10.45 ; R2.2@31,10.45 R2.2@31,10.5 ; R2.2@31,10.45 R2.2@31.05,10.5 ; R2.2@31,10.5 R2.2@31.05,10.5
GND: C1.2 C2.2 C3.2 C4.2 C5.2 C6.2 C7.2 C8.2 C9.2 C10.2 C11.2 C12.2 C13.2 C14.2 C15.2 C16.2 C18.1 C20.1 D1.2 J1.1 J2.2 J3.8 J3.9 J3.10 NT1.2 Q3.1 Q3.2 Q3.3 Q4.1 Q4.2 Q4.3 R15.1 TP2.1 TP4.1 U1.12 U1.15 U1.21@32.5,21 | length 42.9
  Top Layer w0.254: J3.10@3.05,56.32 3.05,55.2 J3.9@5.5,52.75 ; J3.9@5.59,51.25 5.59,53.09 J3.8@8.13,55.63 ; v4(8.13,50.37) J3.8@8.13,55.63 ; J3.8@8.13,56.32 J3.8@8.13,55.63
  Bottom Layer w0.254: v4(8.13,50.37) 8.13,25.87 v4(8.25,25.75) ; U1.21@33.25,21.25 U1.15@34.15,21.25 ; U1.21@33.25,22.25 33.75,22.75 U1.12@34.15,22.75 U1.12@34.384,22.75
  other v1: 37.211,25.146 38.608,25.146 40.005,25.146 48.26,27.94 50.8,27.94 7.62,30.48 48.26,30.48 50.8,30.48
  other v2: 10.16,15.24 12.7,15.24 15.24,15.24 20.32,15.24 40.513,17.145 44.45,17.145 48.514,17.145 11.684,25.4 13.716,25.4 17.78,25.4 11.684,27.94 13.716,27.94 17.78,27.94 11.684,29.718 17.78,30.48 25.4,30.48 30.48,30.48 35.56,30.48 38.1,30.48
  other v3: 42.5,17.223 46.5,17.223 21.5,25.5 40.75,28.75 42.25,28.75 44.75,28.75 46.25,28.75 13.75,29.75
  other v4: 40.75,21.5 23.25,24.75
  other v6: 32.512,19.964 31.953,21.006 33.045,21.006 32.512,22.022
  other v8: 32.791,16.129
  other v13: 23.876,15.24
NetC18_2: C18.2 R3.1 U1.20 | length 4.6
  Bottom Layer w0.254: U1.20@33.25,18.85 33.25,18.566 34.163,17.653 C18.2@34.163,17.272
  Bottom Layer w0.4: C18.2@34.201,17.272 34.201,15.964 34.417,15.748 R3.1@34.417,14.732
NetC19_2: C19.2 R7.1 | length 4.7
  Bottom Layer w0.254: R7.1@39,20.25 R7.1@39.15,20.4
  Bottom Layer w0.5: R7.1@39.05,20.25 C19.2@43.5,20.25
NetC20_2: C20.2 R16.2 U1.11 | length 4.1
  Bottom Layer w0.254: U1.11@33.25,23.15 33.25,23.344 34.417,24.511 C20.2@34.417,24.765 ; R16.2@34.417,26.797 R16.2@34.455,26.759
  Bottom Layer w0.5: C20.2@34.455,24.765 R16.2@34.455,26.759
NetC21_2: C21.2 R10.1 | length 2.7
  Bottom Layer w0.254: R10.1@24.5,17.5 C21.2@24.5,19.5 ; C21.2@24.5,19.5 24.75,19.75 24.7,19.7 C21.2@24.5,19.5
NetC22_2: C22.2 R13.2 | length 2.6
  Bottom Layer w0.254: R13.2@26.95,17.5 C22.2@26.95,19.55 ; C22.2@26.95,19.55 26.75,19.75 C22.2@26.95,19.55
NetC23_2: C23.2 R13.1 U1.4 | length 4.7
  Bottom Layer w0.254: C23.2@28.75,19.65 R13.1@28.75,17.75 ; C23.2@29,19.75 29.5,20.25 U1.4@30.85,20.25 ; R13.1@28.75,17.75 28.5,17.5 R13.1@28.75,17.75
NetC24_2: C24.2 R15.2
NetR4_2: R4.2 U1.2 | length 3.9
  Bottom Layer w0.254: U1.2@30.85,19.25 30.75,19.15 30.75,15.75 30.808,15.692 30.975,15.525 R4.2@31,15.5
NetR6_2: R6.2 U1.18 | length 3.8
  Bottom Layer w0.254: U1.18@34.15,19.75 36,19.75 ; R6.2@37.229,18.275 R6.2@37.25,18.25
  Bottom Layer w0.3: 36,19.75 R6.2@37.229,18.275
NetR7_2: R7.2 U1.17 | length 3.7
  Bottom Layer w0.254: U1.17@34.15,20.25 34.25,20.25 35.491,20.25 35.491,20.287 35.972,20.287 36.009,20.25 R7.2@37.5,20.25 ; R7.2@37.45,20.25 R7.2@37.45,20.5
PGOOD: J3.5 R5.1 U1.10 | length 44
  Top Layer w0.254: J3.5@15.875,50.8 v4(17.145,50.8)
  Bottom Layer w0.254: v4(17.145,50.8) 31.25,50.75 32.25,49.75 32.25,26.25 31.25,25.25 31.25,23.65 U1.10@31.75,23.15
SS: C17.1 J3.6 U1.3 | length 55.9
  Top Layer w0.254: v4(13.208,52.197) J3.6@13.208,53.594
  Bottom Layer w0.254: v4(13.208,52.197) 12.5,51.489 12.5,23.25 19.25,16.5 27.6,16.5 28.35,15.75 ; C17.1@28.5,15.6 28.35,15.75 ; U1.3@30.85,19.75 30.25,19.75 29.75,19.25 29.75,16 29.5,15.75 28.35,15.75
SYNCIN: J3.2 R8.2 U1.8 | length 36.4
  Top Layer w0.254: J3.2@23.25,54.75 23.5,54.5 v4(23.5,48.75)
  Bottom Layer w0.25: 30.444,22.298 30.491,22.25 U1.8@30.861,22.25
  Bottom Layer w0.254: v4@23.5,48.5 v4(23.5,48.75) 23.8,48.75 27.5,45.05 27.5,28 28,27.5 R8.2@28.75,27.5 ; R8.2@28.65,27.05 R8.2@28.75,26.95 ; R8.2@28.75,27 30,25.75 30,22.742 30.444,22.298
SYNCOUT: J3.3 U1.7 | length 33.4
  Top Layer w0.254: J3.3@20.828,48.514 20.955,48.387 v4(22.098,48.387) ; J3.3@20.83,49.67 J3.3@20.83,51.25
  Bottom Layer w0.254: v4(22.098,48.387) 26.5,44 26.5,27.75 29.546,24.704 29.546,22.554 30.35,21.75 U1.7@30.75,21.75
TRIM: J3.4 R9.1 | length 40.2
  Top Layer w0.254: v4(18.29,48.79) J3.4@18.29,56.32
  Bottom Layer w0.254: v4(18.29,48.79) 15.5,46 15.5,24 19.75,19.75 R9.1@20.5,19.75
VCC: C16.1 J3.1 R5.2 R8.1 U1.14 | length 44.2
  Top Layer w0.254: J3.1@25.91,51.25 27,51.25 v4(28.5,49.75)
  3rd Layer w0.508: v4(31.25,29.25) 38.656,21.844 v3@38.735,21.844
  Bottom Layer w0.254: v4(28.5,49.75) 28.75,49.5 R8.1@28.75,28.75 29.75,28.75 31.25,27.25 v4(31.25,29.25) ; U1.14@34.15,21.75 35.131,21.75 35.186,21.804 36.696,21.804 C16.1@36.75,21.75 ; C16.1@36.45,22.2 C16.1@36.5,22.25
  Bottom Layer w0.508: C16.1@37.084,21.844 v3(38.608,21.844)
VFB: C21.1 C22.1 C23.1 R9.2 R11.1 R12.2 U1.5 | length 12.6
  Bottom Layer w0.254: R9.2@20.75,21.25 R11.1@22.75,21.25 ; R11.1@23,21.25 C21.1@24.75,21.25 C22.1@26.75,21.25 C23.1@28.75,21.25 29.25,20.75 U1.5@30.85,20.75
  Bottom Layer w0.5: C21.1@24.75,21.25 24.75,22.083 25.4,22.733 R12.2@26.162,22.733
Vg1: Q1.4 Q2.4 R6.1 TP8.1 | length 34.6
  Top Layer w0.508: v1@54.991,15.494 v1@55,15.494 ; Q1.4@56.201,15.5 Q1.4@56.25,15.5
  Top Layer w0.65: v1@55,15.494 Q1.4@56.201,15.5 ; v1(61.849,15.367) Q2.4@63.119,15.367
  Bottom Layer w0.508: R6.1@38.55,18.25 R6.1@38.8,18.25 ; TP8.1@53.213,8.636 55,10.423 v1(55,15.5) ; v1@61.716,15.5 v1(61.849,15.367)
  Bottom Layer w0.7: R6.1@38.8,18.25 50.25,18.25 53,15.5 v1(55,15.5) v1@61.716,15.5
Vg2: Q3.4 Q4.4 TP9.1 U1.13 | length 29
  Top Layer w0.254: Q3.4@53.25,18 Q3.4@53.75,18
  Top Layer w0.508: v1(52,24.75) Q4.4@53.75,24.75
  Top Layer w0.65: v1(52,18) Q3.4@53.25,18
  Bottom Layer w0.254: U1.13@34.15,22.25 35,22.25
  Bottom Layer w0.3: 35,22.25 35.61,22.86 38.354,22.86
  Bottom Layer w0.5: 38.354,22.86 39.37,23.876
  Bottom Layer w0.7: 39.37,23.876 TP9.1@49.276,23.876 ; TP9.1@49.403,23.876 50.277,24.75 v1(52,24.75) v1(52,18)
Vin: C4.1 C5.1 C6.1 C7.1 C8.1 C9.1 C10.1 L1.1 Q1.5 Q1.6 Q1.7 Q1.8 Q1.9 Q2.5 Q2.6 Q2.7 Q2.8 Q2.9 R1.2 R3.2 | length 2.5
  Bottom Layer w0.254: R3.2@32.893,14.859 32.893,14.557 33.25,14.2 33.25,12.5
  other v1: 33.02,2.54 35.56,2.54 38.1,2.54 40.64,2.54 43.18,2.54 45.72,2.54 48.26,2.54 50.8,2.54 53.34,2.54 55.88,2.54 58.42,2.54 60.96,2.54 63.5,2.54 66.04,2.54 68.58,2.54 71.12,2.54 73.66,2.54 35.56,5.08 38.1,5.08 40.64,5.08 43.18,5.08 45.72,5.08 48.26,5.08 50.8,5.08 53.34,5.08 55.88,5.08 58.42,5.08 60.96,5.08 63.5,5.08 66.04,5.08 68.58,5.08 71.12,5.08 73.66,5.08 35.56,7.62 38.1,7.62 40.64,7.62 43.18,7.62 45.72,7.62 48.26,7.62 55.88,7.62 58.42,7.62 60.96,7.62 63.5,7.62 66.04,7.62 68.58,7.62 71.12,7.62 73.66,7.62 35.56,10.16 38.1,10.16 40.64,10.16 43.18,10.16 45.72,10.16 48.26,10.16 68.58,10.16 71.12,10.16 73.66,10.16 68.58,12.7 71.12,12.7 73.66,12.7
  other v3: 34,5.75 34,7.25 34,8.75 56.5,10.75 58,10.75 59.5,10.75 63.5,10.75 65,10.75 66.5,10.75 56.5,12 58,12 59.5,12 63.5,12 65,12 66.5,12 56.5,13.25 58,13.25 59.5,13.25 63.5,13.25 65,13.25 66.5,13.25
  other v4: 38.5,11.5 42.5,11.5 46.5,11.5 50.5,11.5
  other v11: 34.75,11.5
